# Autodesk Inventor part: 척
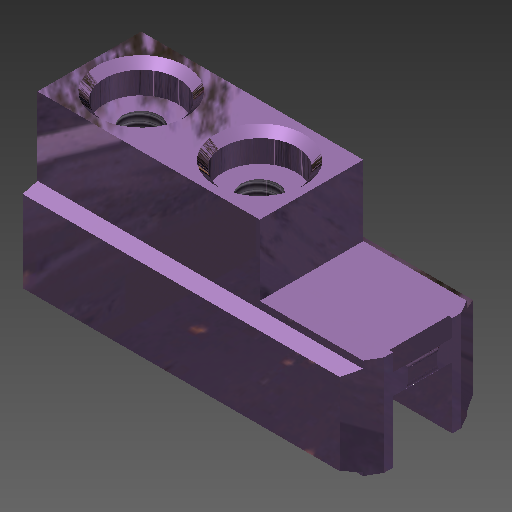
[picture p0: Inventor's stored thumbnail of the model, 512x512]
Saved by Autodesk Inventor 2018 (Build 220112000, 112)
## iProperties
Created: 2023-03
Part Number: 척
Material: 강철, 탄소
Document SubType Name: Modeling
Designer: mdu-01
Density: 1 g/cm^3
Appearance: 반광택(1)
Author: mdu-01
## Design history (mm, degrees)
sketch "스케치1"
  geometry: L1 (0, 0)-(23, 0); L2 (12.536, -7)-(12, -9); L3 (12, -9)-(1, -9); L4 (1, -9)-(0.464, -7); L5 (23, -7)-(12.536, -7); L6 (0.464, -7)-(0, -7); L7 (12.536, 7)-(12, 9); L8 (12, 9)-(1, 9); L9 (1, 9)-(0.464, 7); L10 (23, 7)-(12.536, 7); L11 (0.464, 7)-(0, 7); L12 (0, 7)-(0, -7); L13 (23, 7)-(23, -7); L14 (6.5, 9)-(6.5, -9)
  constraints: 28 end point, 6 symmetric about line, 4 parallel, 2 midpoint, 2 perpendicular, 2 vertical alignment, 1 equal length, 1 horizontal, 1 other
  dimensions: "d0" = 23 distance of L1.start L1.end; "d1" = 1 horizontal distance of L3.end L6.end; "d2" = 11 distance of L2.end L3.end; "d3" = 30 deg angle of L4 L2; "d5" = 14 distance between parallel lines of L5 L10; "d6" = 18 distance between parallel lines of L3 L8
extrude "돌출1" new body sketch "스케치1" distance "d7" = 45; taper "d8" = 0 deg
sketch "스케치2"
  geometry: L1 (0, 16)-(45, 16) reference; L2 (0, -2)-(45, -2) reference; L3 (45, 16)-(45, 14) reference; L4 (45, 14)-(45, 0) reference; L5 (45, 0)-(45, -2) reference; L6 (42.804, 16)-(45, 12.196); L7 (42.804, -2)-(45, 1.804); L8 (0, 0)-(0, 14) reference; 3 further points
  constraints: 6 point on line, 4 end point, 1 horizontal alignment, 1 midpoint, 1 vertical alignment
  dimensions: "d9" = 3 distance from line of point (48, 7) L5; "d10" = 120 deg angle of L7 L6
extrude "돌출2" cut sketch "스케치2" extent not by distance; stored distance "d11" = 45; taper "d12" = 0 deg
sketch "스케치3"
  geometry: L1 (-7, 23)-(7, 23); L2 (7, 23)-(7, 13.5); L3 (7, 13.5)-(-7, 13.5); L4 (-7, 13.5)-(-7, 23); L5 (5.196, 23)-(-5.196, 23) reference; L6 (-7, 12.536)-(-7, 23) reference; 2 further points
  constraints: 8 end point, 2 midpoint, 2 parallel, 1 collinear, 1 horizontal, 1 perpendicular
  dimensions: "d13" = 9.5 distance between parallel lines of L3 L1
extrude "돌출3" cut sketch "스케치3" distance "d15" = 15; taper "d16" = 0 deg
sketch "스케치4"
  geometry: L1 (30, 13.5)-(43.959, 13.5) reference; L2 (43.959, 13.5)-(45, 13.5) reference; L3 (45, 0)-(45, 13.5) reference; L4 (43.959, 0)-(45, 0) reference; L5 (0, 0)-(43.959, 0) reference; L6 (44.5, 13.5)-(31, 0); L7 (45, 11.172)-(33.828, 0); L8 (45, 8.343)-(36.657, 0); L9 (44.5, 13.5)-(45, 13.5); L10 (45, 11.172)-(45, 13.5)
  constraints: 10 end point, 6 point on line, 2 parallel, 1 collinear, 1 perpendicular
  dimensions: "d17" = 45 deg angle of L6 L1; "d18" = 14 distance from line of L6.end L3; "d19" = 2 distance between parallel lines of L7 L6; "d20" = 2 distance between parallel lines of L8 L7
extrude "돌출4" cut sketch "스케치4" stored distance "d21" = 8; taper "d22" = 0 deg
extrude "돌출5" cut sketch "스케치4" stored distance "d23" = 4; taper "d24" = 0 deg
fillet "모깎기1" dims "d25" = 0.5
sketch "스케치5"
  geometry: L1 (0, 0)-(0, 14) reference; C1 r 5 at (7, 7); C2 r 5 at (23, 7); 2 further points
  constraints: 2 centre point, 2 horizontal alignment, 1 equal radius, 1 midpoint
  dimensions: "d26" = 10 diameter of C1; "d27" = 7 distance from line of C1.centre L1; "d28" = 16 distance of C2.centre C1.centre
extrude "돌출6" cut sketch "스케치5" distance "d29" = 4; taper "d30" = 0 deg
chamfer "모따기1" distance "d31" = 1; stored, may be unused: second distance "d32" = 2, angle "d33" = 45 deg
sketch "스케치6"
  geometry: C1 r 5 at (0, 0) reference; C2 r 5 at (16, 0) reference; 1 further point
hole "구멍1" sketch "스케치6" at (0, 0), (16, 0) diameter "d34" = 4.917; stored, may be unused: countersink angle "d38" = 90 deg, drill point angle "d40" = 118 deg; dims "d35" = 12, "d36" = 4, "d37" = 2, "d39" = 14
node "솔리드1"
other parameters: "d4" = 2
